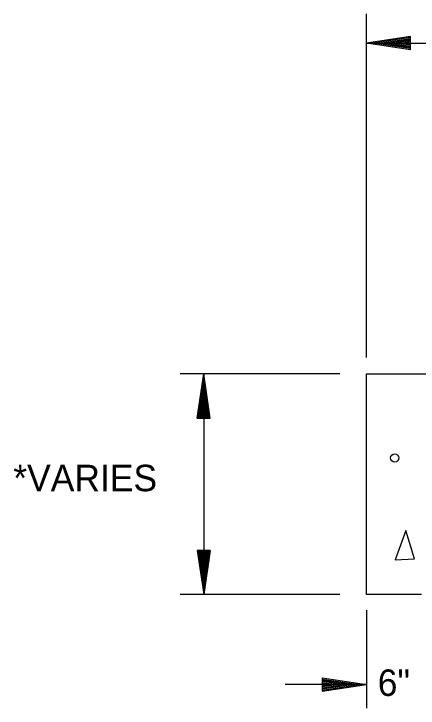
# Model space of a CAD drawing. Extents: x 1373918 to 1374069, y 381000 to 381245.
# Drawn here: x 1373918.16 to 1373927.31, y 381080.07 to 381095.8 of the extents above; entities that cross this region are included whole.
import ezdxf

# ---------------------------------------------------------------- set-up
doc = ezdxf.new("R2010")
doc.units = 0
doc.layers.add('Default', color=7, linetype='Continuous')

msp = doc.modelspace()

# ---------------------------------------------------------------- linework, layer by layer
at = {"layer": 'Default'}
for p, q in [((1373926.141, 381088.018), (1373926.141, 381095.799)), ((1373927.142, 381095.287), (1373926.142, 381095.137)), ((1373927.142, 381094.987), (1373927.142, 381095.287)), ((1373926.141, 381095.137), (1373976.137, 381095.137)), ((1373927.142, 381094.987), (1373926.142, 381095.137)), ((1373927.142, 381095.262), (1373926.31, 381095.137)), ((1373927.142, 381095.012), (1373926.31, 381095.137)), ((1373927.142, 381095.237), (1373926.48, 381095.137)), ((1373927.142, 381095.037), (1373926.48, 381095.137)), ((1373927.142, 381095.212), (1373926.647, 381095.137)), ((1373927.142, 381095.062), (1373926.647, 381095.137)), ((1373927.142, 381095.187), (1373926.817, 381095.137)), ((1373927.142, 381095.089), (1373926.817, 381095.137)), ((1373927.142, 381095.162), (1373926.985, 381095.137)), ((1373927.142, 381095.114), (1373926.985, 381095.137)), ((1373925.537, 381087.644), (1373921.924, 381087.644)), ((1373922.307, 381086.642), (1373922.457, 381087.642)), ((1373922.607, 381086.642), (1373922.457, 381087.642)), ((1373922.458, 381087.644), (1373922.458, 381082.644)), ((1373926.141, 381087.644), (1374017.385, 381087.644)), ((1373926.141, 381082.644), (1373926.141, 381087.644)), ((1373922.332, 381086.642), (1373922.457, 381087.477)), ((1373922.582, 381086.642), (1373922.457, 381087.477)), ((1373922.36, 381086.642), (1373922.457, 381087.305)), ((1373922.557, 381086.642), (1373922.457, 381087.305)), ((1373922.385, 381086.642), (1373922.457, 381087.137)), ((1373922.532, 381086.642), (1373922.457, 381087.137)), ((1373922.41, 381086.642), (1373922.457, 381086.967)), ((1373922.507, 381086.642), (1373922.457, 381086.967)), ((1373922.435, 381086.642), (1373922.457, 381086.802)), ((1373922.482, 381086.642), (1373922.457, 381086.802)), ((1373922.307, 381086.642), (1373922.607, 381086.642)), ((1373922.307, 381083.642), (1373922.457, 381082.642)), ((1373922.607, 381083.642), (1373922.307, 381083.642)), ((1373922.332, 381083.642), (1373922.457, 381082.81)), ((1373922.36, 381083.642), (1373922.457, 381082.982)), ((1373922.385, 381083.642), (1373922.457, 381083.15)), ((1373922.41, 381083.642), (1373922.457, 381083.317)), ((1373922.435, 381083.642), (1373922.457, 381083.485)), ((1373922.607, 381083.642), (1373922.457, 381082.642)), ((1373922.507, 381083.642), (1373922.457, 381083.317)), ((1373922.557, 381083.642), (1373922.457, 381082.982)), ((1373922.582, 381083.642), (1373922.457, 381082.81)), ((1373922.532, 381083.642), (1373922.457, 381083.15)), ((1373922.482, 381083.642), (1373922.457, 381083.485)), ((1373925.537, 381082.644), (1373921.924, 381082.644)), ((1373927.391, 381082.644), (1373926.141, 381082.644)), ((1373926.141, 381082.29), (1373926.141, 381080.072)), ((1373925.142, 381080.755), (1373926.142, 381080.605)), ((1373925.142, 381080.755), (1373925.142, 381080.455)), ((1373925.142, 381080.73), (1373925.975, 381080.605)), ((1373925.142, 381080.705), (1373925.802, 381080.605)), ((1373925.142, 381080.68), (1373925.637, 381080.605)), ((1373925.142, 381080.655), (1373925.467, 381080.605)), ((1373926.141, 381080.606), (1373924.305, 381080.606)), ((1373925.142, 381080.63), (1373925.3, 381080.605)), ((1373925.142, 381080.455), (1373926.142, 381080.605)), ((1373925.142, 381080.558), (1373925.467, 381080.605)), ((1373925.142, 381080.505), (1373925.802, 381080.605)), ((1373925.142, 381080.48), (1373925.975, 381080.605)), ((1373925.142, 381080.53), (1373925.637, 381080.605)), ((1373925.142, 381080.583), (1373925.3, 381080.605))]:
    msp.add_line(p, q, dxfattribs=at)
msp.add_lwpolyline([(1373927.034, 381084.095), (1373926.792, 381083.43), (1373927.232, 381083.45), (1373927.034, 381084.095)], dxfattribs=at)
msp.add_circle((1373926.782, 381085.739), 0.0937, dxfattribs=at)

# ---------------------------------------------------------------- texts
for s, p in [('*VARIES', (1373918.147, 381084.985)), ('6"', (1373926.397, 381080.348))]:
    msp.add_text(s, height=0.6, dxfattribs=at).set_placement(p)

doc.saveas('drawing.dxf')
